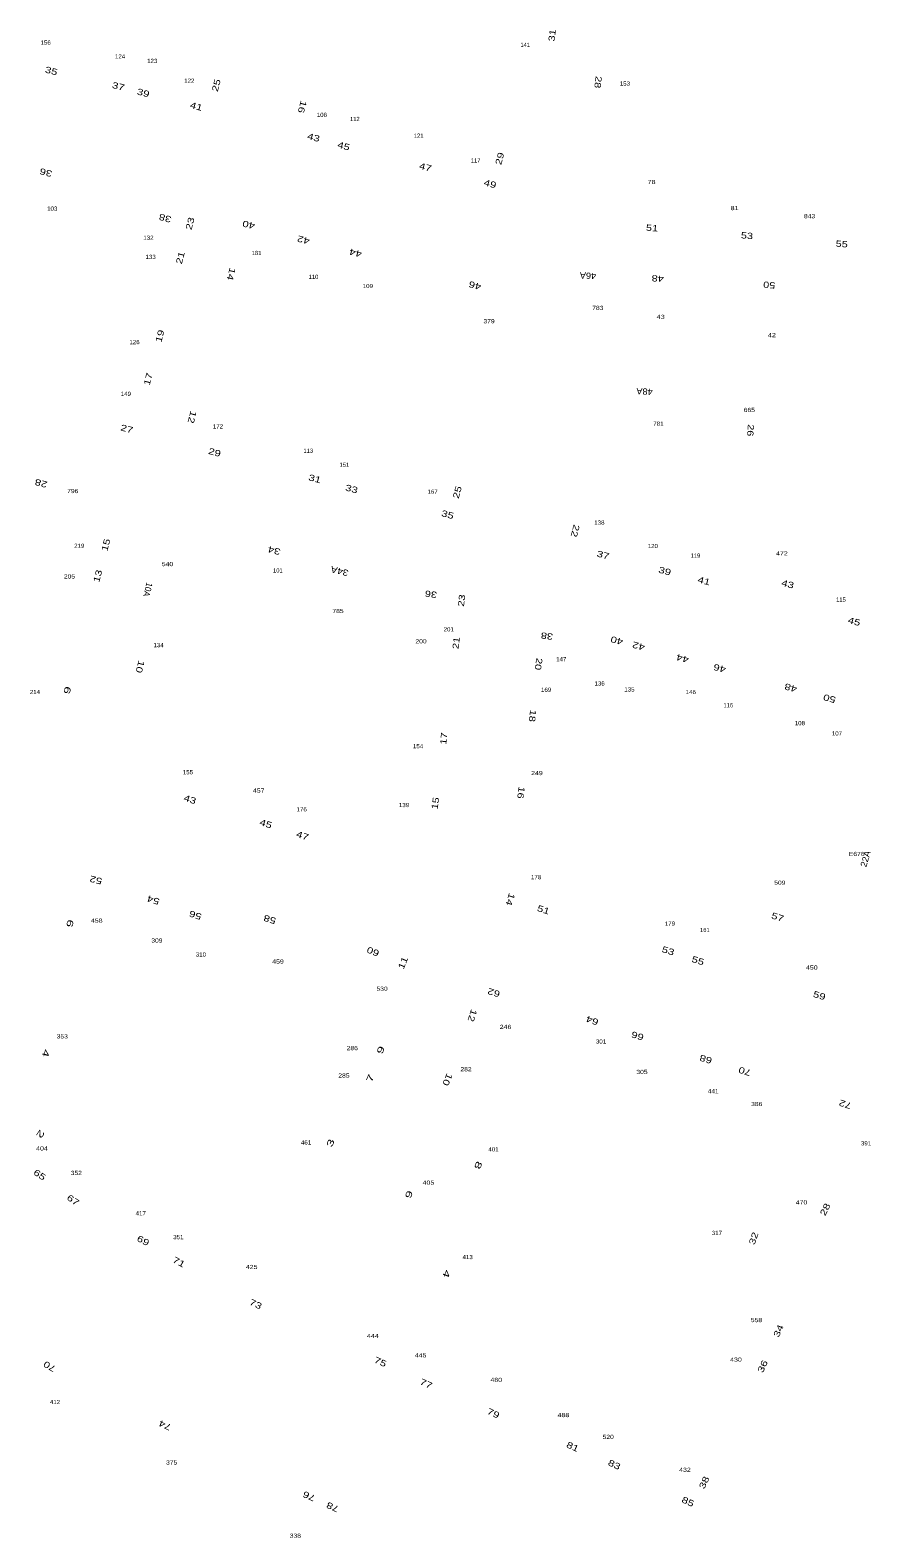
# Model space of a CAD drawing. Extents: x -828673 to -815583, y -1077737 to -1063807.
# Drawn here: x -818324 to -818122.8, y -1069307.7 to -1068947.1 of the extents above; entities that cross this region are included whole.
import ezdxf
from ezdxf.enums import TextEntityAlignment as Align

# ---------------------------------------------------------------- set-up
doc = ezdxf.new("R2010")
doc.units = 0
doc.header["$LTSCALE"] = 0.4
doc.layers.add('1', color=7, linetype='Continuous')
doc.layers.add('2', color=7, linetype='Continuous')

msp = doc.modelspace()

# ---------------------------------------------------------------- texts
at = {"layer": '1'}
for s, width, p in [('156', 1.1, (-818320.256, -1068950.552)), ('124', 1.1, (-818302.449, -1068953.862)), ('123', 1.1, (-818294.762, -1068954.933)), ('122', 1.1, (-818285.897, -1068959.662)), ('153', 1.1, (-818181.684, -1068960.343)), ('106', 1.1, (-818254.176, -1068967.84)), ('78', 1.3, (-818175.307, -1068983.902)), ('103', 1.1, (-818318.684, -1068990.257)), ('81', 1.3, (-818155.432, -1068990.133)), ('843', 1.2, (-818137.5, -1068992.07)), ('132', 1.1, (-818295.669, -1068997.224)), ('133', 1.1, (-818295.149, -1069001.8)), ('109', 1.1, (-818243.178, -1069008.767)), ('783', 1.2, (-818188.159, -1069014.003)), ('379', 1.2, (-818214.179, -1069017.19)), ('43', 1.3, (-818173.123, -1069016.15)), ('126', 1.1, (-818298.995, -1069022.182)), ('42', 1.3, (-818146.514, -1069020.518)), ('149', 1.1, (-818301.073, -1069034.557)), ('665', 1.2, (-818151.919, -1069038.404)), ('172', 1.1, (-818279.038, -1069042.356)), ('781', 1.1, (-818173.672, -1069041.697)), ('796', 1.2, (-818313.772, -1069057.805)), ('167', 1.1, (-818227.691, -1069057.955)), ('138', 1.1, (-818187.779, -1069065.338)), ('219', 1.1, (-818312.211, -1069070.886)), ('120', 1.1, (-818174.994, -1069070.953)), ('472', 1.25, (-818144.124, -1069072.721)), ('540', 1.25, (-818291.108, -1069075.272)), ('205', 1.2, (-818314.555, -1069078.23)), ('785', 1.2, (-818250.314, -1069086.494)), ('200', 1.2, (-818230.451, -1069093.733)), ('201', 1.1, (-818223.824, -1069090.877)), ('134', 1.1, (-818293.249, -1069094.651)), ('147', 1.1, (-818196.898, -1069098.021)), ('136', 1.1, (-818187.736, -1069103.83)), ('135', 1.1, (-818180.6, -1069105.258)), ('214', 1.1, (-818322.813, -1069105.87)), ('169', 1.1, (-818200.528, -1069105.332)), ('146', 1.1, (-818165.92, -1069105.87)), ('108', 1.1, (-818139.822, -1069113.316)), ('107', 1.1, (-818130.953, -1069115.763)), ('154', 1.1, (-818231.165, -1069118.824)), ('155', 1.1, (-818286.215, -1069125.045)), ('249', 1.25, (-818202.723, -1069125.249)), ('457', 1.25, (-818269.292, -1069129.431)), ('176', 1.1, (-818258.996, -1069133.919)), ('139', 1.1, (-818234.529, -1069132.899)), ('E676', 1.2, (-818126.224, -1069144.592)), ('178', 1.1, (-818202.926, -1069150.136)), ('509', 1.2, (-818144.613, -1069151.462)), ('458', 1.25, (-818308.033, -1069160.542)), ('179', 1.1, (-818170.915, -1069161.253)), ('309', 1.2, (-818293.643, -1069165.299)), ('310', 1.1, (-818283.107, -1069168.641)), ('459', 1.25, (-818264.67, -1069170.312)), ('450', 1.25, (-818136.968, -1069171.758)), ('530', 1.2, (-818239.775, -1069176.82)), ('246', 1.25, (-818210.237, -1069185.947)), ('353', 1.2, (-818316.276, -1069188.219)), ('286', 1.2, (-818246.905, -1069191.024)), ('301', 1.1, (-818187.39, -1069189.446)), ('285', 1.2, (-818248.897, -1069197.579)), ('282', 1.2, (-818219.688, -1069196.072)), ('305', 1.2, (-818177.6, -1069196.722)), ('441', 1.15, (-818160.559, -1069201.338)), ('386', 1.2, (-818150.14, -1069204.391)), ('404', 1.25, (-818321.142, -1069215.025)), ('461', 1.1, (-818257.955, -1069213.583)), ('401', 1.1, (-818213.121, -1069215.238)), ('391', 1.1, (-818123.996, -1069213.789)), ('352', 1.2, (-818312.92, -1069220.874)), ('405', 1.25, (-818228.675, -1069223.204)), ('417', 1.1, (-818297.502, -1069230.514)), ('470', 1.25, (-818139.424, -1069227.918)), ('351', 1.1, (-818288.508, -1069236.235)), ('317', 1.1, (-818159.665, -1069235.215)), ('413', 1.1, (-818219.298, -1069240.999)), ('425', 1.25, (-818270.97, -1069243.369)), ('558', 1.2, (-818150.201, -1069256.07)), ('444', 1.3, (-818242.003, -1069259.874)), ('445', 1.25, (-818230.542, -1069264.49)), ('430', 1.25, (-818155.112, -1069265.526)), ('480', 1.25, (-818212.459, -1069270.372)), ('412', 1.1, (-818318.009, -1069275.659)), ('488', 1.25, (-818196.384, -1069278.786)), ('520', 1.2, (-818185.668, -1069283.997)), ('375', 1.2, (-818290.113, -1069290.122)), ('432', 1.25, (-818167.317, -1069291.882)), ('338', 1.2, (-818260.523, -1069307.636))]:
    msp.add_text(s, height=1, dxfattribs=dict(at, width=width)).set_placement(p, align=Align.CENTER)
for s, p in [('141', (-818205.524, -1068951.094)), ('112', (-818246.294, -1068968.814)), ('121', (-818231.018, -1068972.805)), ('117', (-818217.395, -1068978.744)), ('181', (-818269.787, -1069000.864)), ('110', (-818256.171, -1069006.583)), ('113', (-818257.418, -1069048.18)), ('151', (-818248.791, -1069051.508)), ('119', (-818164.808, -1069073.241)), ('101', (-818264.704, -1069076.802)), ('115', (-818129.988, -1069083.744)), ('116', (-818156.949, -1069109.032)), ('161', (-818162.556, -1069162.783))]:
    msp.add_text(s, height=1, dxfattribs=at).set_placement(p, align=Align.CENTER)
at = {"layer": '2'}
for s, rotation, width, p in [('31', 82.93, 1.3, (-818198.3568, -1068948.4168)), ('35', 345.195, 1.35, (-818319.0941, -1068957.5402)), ('37', 346.193, 1.35, (-818303.0395, -1068961.2344)), ('25', 75.627, 1.35, (-818278.7268, -1068960.4697)), ('28', 262.989, 1.3, (-818188.8267, -1068959.4335)), ('39', 344.912, 1.35, (-818297.1037, -1068962.7994)), ('41', 344.698, 1.35, (-818284.4169, -1068966.0319)), ('16', 254.889, 1.35, (-818259.57, -1068965.23)), ('43', 344.991, 1.35, (-818256.3487, -1068973.4583)), ('45', 344.291, 1.35, (-818249.1481, -1068975.5054)), ('29', 75.101, 1.35, (-818210.9044, -1068977.9928)), ('36', 165.62, 1.35, (-818320.0072, -1068980.4057)), ('47', 345.329, 1.35, (-818229.5894, -1068980.5638)), ('49', 345.123, 1.35, (-818214.1186, -1068984.5561)), ('38', 165.201, 1.35, (-818291.4849, -1068991.3249)), ('23', 75.468, 1.35, (-818284.9988, -1068993.5287)), ('40', 166.54, 1.35, (-818271.5034, -1068992.8984)), ('51', 355.322, 1.3, (-818175.2467, -1068995.1411)), ('53', 355.24, 1.3, (-818152.5357, -1068996.9713)), ('42', 165.296, 1.35, (-818258.4081, -1068996.5305)), ('44', 165.738, 1.35, (-818245.9352, -1068999.6529)), ('55', 355.298, 1.3, (-818129.8635, -1068998.9578)), ('21', 75.267, 1.35, (-818287.3228, -1069001.7082)), ('14', 255.559, 1.35, (-818276.5708, -1069005.2205)), ('46A', 176.793, 1.1, (-818190.476, -1069005.064)), ('48', 176.762, 1.3, (-818173.7936, -1069005.7372)), ('46', 164.482, 1.35, (-818217.3518, -1069007.4455)), ('50', 175.187, 1.3, (-818147.0836, -1069007.2893)), ('19', 75.288, 1.35, (-818292.2093, -1069020.426)), ('17', 75.519, 1.35, (-818295.0171, -1069030.7205)), ('48A', 176.447, 1.1, (-818176.939, -1069032.7652)), ('12', 255.248, 1.35, (-818285.9278, -1069039.433)), ('27', 345.267, 1.35, (-818301.0182, -1069043.1522)), ('26', 265.541, 1.3, (-818152.3544, -1069042.7152)), ('29', 345.075, 1.35, (-818280.0217, -1069048.7693)), ('31', 345.26, 1.35, (-818256.0548, -1069055.0785)), ('28', 165.237, 1.35, (-818321.1659, -1069054.7339)), ('33', 344.886, 1.35, (-818247.2586, -1069057.5122)), ('25', 74.678, 1.35, (-818221.0716, -1069057.7972)), ('35', 344.69, 1.35, (-818224.288, -1069063.6491)), ('22', 255.812, 1.35, (-818194.2894, -1069066.6412)), ('15', 75.445, 1.35, (-818305.1463, -1069070.377)), ('34', 165.481, 1.35, (-818265.3985, -1069070.8121)), ('37', 345.169, 1.35, (-818187.077, -1069073.316)), ('34A', 166.159, 1.2, (-818249.7676, -1069075.7433)), ('13', 75.221, 1.35, (-818307.0815, -1069077.8243)), ('39', 345.299, 1.35, (-818172.3168, -1069077.1645)), ('41', 345.401, 1.35, (-818162.948, -1069079.5079)), ('43', 344.792, 1.35, (-818142.9252, -1069080.2796)), ('10A', 255.504, 0.95, (-818296.5115, -1069080.6773)), ('36', 172.125, 1.3, (-818227.9817, -1069081.2509)), ('23', 82.635, 1.3, (-818220.0201, -1069083.5801)), ('45', 344.956, 1.35, (-818127.0227, -1069089.2233)), ('21', 83.388, 1.3, (-818221.3187, -1069093.7319)), ('38', 172.796, 1.3, (-818200.2389, -1069091.2523)), ('40', 164.894, 1.35, (-818183.406, -1069092.3361)), ('42', 164.982, 1.35, (-818178.2067, -1069093.6623)), ('44', 165.6, 1.35, (-818167.7045, -1069096.6243)), ('10', 255.705, 1.35, (-818298.3731, -1069099.1373)), ('20', 261.806, 1.3, (-818203.0534, -1069098.5841)), ('46', 165.935, 1.35, (-818158.8367, -1069098.9708)), ('9', 74.888, 1.65, (-818314.3392, -1069105.1415)), ('48', 164.501, 1.35, (-818141.8111, -1069103.655)), ('50', 164.852, 1.35, (-818132.5335, -1069106.2071)), ('18', 263.169, 1.3, (-818204.504, -1069110.9733)), ('17', 84.301, 1.3, (-818224.2823, -1069116.5795)), ('16', 262.617, 1.3, (-818207.2613, -1069129.3326)), ('43', 342.07, 1.35, (-818285.9529, -1069131.7601)), ('15', 82.005, 1.3, (-818226.3018, -1069132.0818)), ('45', 341.994, 1.35, (-818267.8068, -1069137.5748)), ('47', 342.129, 1.35, (-818259.0377, -1069140.4285)), ('22A', 73.636, 1.1, (-818123.3952, -1069145.4698)), ('52', 166.039, 1.35, (-818308.0391, -1069149.6155)), ('54', 162.385, 1.35, (-818294.2905, -1069154.4169)), ('14', 252.497, 1.35, (-818209.8012, -1069154.7229)), ('56', 162.005, 1.35, (-818284.2058, -1069158.0152)), ('51', 341.917, 1.35, (-818201.3968, -1069158.153)), ('57', 342.229, 1.35, (-818145.3649, -1069159.909)), ('6', 255.429, 1.65, (-818315.1441, -1069160.5158)), ('58', 162.559, 1.35, (-818266.4112, -1069159.0454)), ('60', 157.899, 1.35, (-818241.6593, -1069166.7438)), ('11', 67.901, 1.35, (-818234.0808, -1069170.4317)), ('53', 342.453, 1.35, (-818171.5646, -1069167.9662)), ('55', 342.498, 1.35, (-818164.4281, -1069170.3112)), ('62', 162.708, 1.35, (-818212.8221, -1069176.5532)), ('59', 343.234, 1.35, (-818135.3734, -1069178.6714)), ('12', 252.597, 1.35, (-818218.8777, -1069182.5057)), ('64', 160.067, 1.35, (-818189.2318, -1069183.2392)), ('66', 162.953, 1.35, (-818178.4416, -1069186.9025)), ('9', 68.409, 1.65, (-818239.4181, -1069191.2495)), ('4', 255.925, 1.65, (-818320.9112, -1069191.5641)), ('68', 163.244, 1.35, (-818162.1038, -1069192.4688)), ('7', 67.669, 1.65, (-818241.9166, -1069198.0015)), ('10', 247.416, 1.35, (-818224.8054, -1069197.7585)), ('70', 162.474, 1.35, (-818152.7837, -1069195.3743)), ('72', 161.962, 1.35, (-818128.7473, -1069203.2642)), ('2', 236.078, 1.7, (-818322.11, -1069210.6585)), ('3', 67.894, 1.65, (-818251.4271, -1069213.4902)), ('65', 326.111, 1.35, (-818322.0967, -1069221.4379)), ('8', 247.724, 1.65, (-818217.4594, -1069218.2577)), ('67', 325.335, 1.35, (-818314.1316, -1069227.4846)), ('6', 248.919, 1.65, (-818234.0446, -1069225.2582)), ('28', 63.488, 1.35, (-818133.1175, -1069229.4458)), ('69', 331.442, 1.35, (-818297.2915, -1069237.2194)), ('32', 70.775, 1.35, (-818150.1891, -1069236.27)), ('71', 331.147, 1.35, (-818288.7349, -1069242.3475)), ('4', 248.927, 1.65, (-818225.0395, -1069244.2443)), ('73', 334.853, 1.35, (-818270.3237, -1069252.4252)), ('34', 65.346, 1.35, (-818144.2662, -1069258.4674)), ('70', 149.765, 1.35, (-818318.9433, -1069266.0182)), ('75', 335.556, 1.35, (-818240.4774, -1069266.2467)), ('36', 64.94, 1.35, (-818148.0591, -1069266.9552)), ('77', 335.831, 1.35, (-818229.5381, -1069271.4567)), ('79', 334.819, 1.35, (-818213.4646, -1069278.5348)), ('74', 155.029, 1.35, (-818291.3909, -1069280.0572)), ('81', 335.706, 1.35, (-818194.4771, -1069286.5279)), ('83', 335.368, 1.35, (-818184.5151, -1069290.8173)), ('38', 65.376, 1.35, (-818162.0531, -1069294.7275)), ('76', 156.09, 1.35, (-818256.9445, -1069297.0106)), ('85', 334.951, 1.35, (-818166.907, -1069299.6726)), ('78', 155.864, 1.35, (-818251.2978, -1069299.6088))]:
    msp.add_text(s, height=1.5, rotation=rotation, dxfattribs=dict(at, width=width)).set_placement(p, align=Align.CENTER)

doc.saveas('drawing.dxf')
